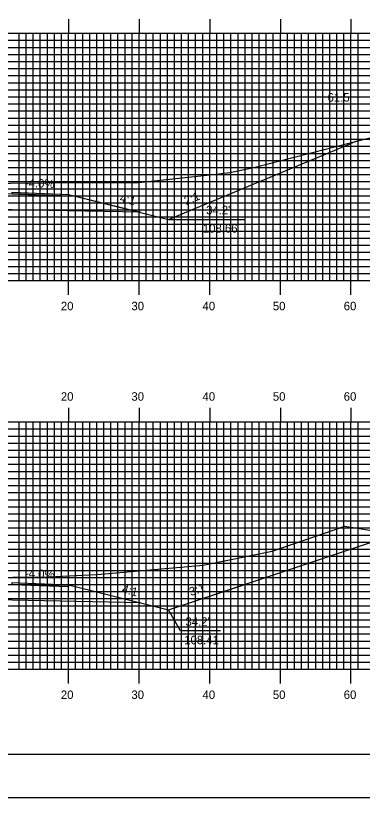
# Model space of a CAD drawing. Extents: x 1766513 to 1766856, y 442591 to 442811.
# Drawn here: x 1766691.4 to 1766740.5, y 442590.5 to 442701.2 of the extents above; entities that cross this region are included whole.
import ezdxf

# ---------------------------------------------------------------- set-up
doc = ezdxf.new("R2010")
doc.units = 0
for name, color, linetype in [('ANNOTATION', 7, 'Continuous'), ('BORDER', 7, 'Continuous'), ('D_Roadway_Centerline', 7, 'Continuous'), ('D_Roadway_Edge_Shoulder', 7, 'Continuous'), ('D_Roadway_SlopeLines', 7, 'Continuous'), ('D_Roadway_SubGrade', 7, 'Continuous'), ('D_Text_Standard', 7, 'Continuous'), ('H_V ANNOTATION', 7, 'Continuous'), ('MAJOR', 7, 'Continuous'), ('MINOR', 7, 'Continuous'), ('PDRAIN', 7, 'Continuous'), ('PLOT BOUNDARY', 7, 'Continuous'), ('S_Roadway_Centerline', 7, 'Continuous')]:
    doc.layers.add(name, color=color, linetype=linetype)

msp = doc.modelspace()

# ---------------------------------------------------------------- linework, layer by layer
at = {"layer": 'ANNOTATION'}
msp.add_lwpolyline([(1766720.43, 442614.1), (1766714.74, 442614.1), (1766713.08, 442617.08)], dxfattribs=at)
msp.add_arc((1766742.62, 442673.8), 10, 104.3672, 112.6238, dxfattribs=at)
at = {"layer": 'BORDER'}
msp.add_lwpolyline([(1766529.31, 442596.67), (1766849.31, 442596.67), (1766849.31, 442806.67), (1766529.31, 442806.67)], close=True, dxfattribs=at)
at = {"layer": 'D_Roadway_Centerline'}
msp.add_line((1766713.08, 442617.08), (1766742.93, 442627.03), dxfattribs=at)
at = {"layer": 'D_Roadway_Edge_Shoulder'}
for points in [[(1766690.91, 442676.19), (1766698.91, 442675.87), (1766698.91, 442675.62), (1766690.91, 442675.94)], [(1766690.91, 442620.94), (1766698.91, 442620.62), (1766698.91, 442620.37), (1766690.91, 442620.69)]]:
    msp.add_lwpolyline(points, close=True, dxfattribs=at)
at = {"layer": 'D_Roadway_SlopeLines'}
for points in [[(1766713.08, 442672.33), (1766738.77, 442683.03)], [(1766698.91, 442675.87), (1766713.08, 442672.33)], [(1766698.91, 442620.62), (1766713.08, 442617.08)], [(1766713.08, 442617.08), (1766723.71, 442620.62)]]:
    msp.add_lwpolyline(points, dxfattribs=at)
at = {"layer": 'D_Roadway_SubGrade'}
for points in [[(1766666.91, 442674.22), (1766648.74, 442673.86), (1766658.91, 442676.4), (1766658.91, 442676.15), (1766666.91, 442676.47), (1766678.91, 442676.21), (1766690.91, 442675.94), (1766698.91, 442675.62), (1766698.91, 442675.87), (1766709.08, 442673.33), (1766690.91, 442673.69), (1766678.91, 442673.96)], [(1766666.91, 442618.97), (1766648.74, 442618.61), (1766658.91, 442621.15), (1766658.91, 442620.9), (1766666.91, 442621.22), (1766678.91, 442620.96), (1766690.91, 442620.69), (1766698.91, 442620.37), (1766698.91, 442620.62), (1766709.08, 442618.08), (1766690.91, 442618.44), (1766678.91, 442618.71)]]:
    msp.add_lwpolyline(points, close=True, dxfattribs=at)
at = {"layer": 'MAJOR'}
for p, q in [((1766698.91, 442700.67), (1766698.91, 442698.67)), ((1766708.91, 442700.67), (1766708.91, 442698.67)), ((1766718.91, 442700.67), (1766718.91, 442698.67)), ((1766728.91, 442700.67), (1766728.91, 442698.67)), ((1766738.91, 442700.67), (1766738.91, 442698.67)), ((1766538.91, 442698.67), (1766818.91, 442698.67)), ((1766538.91, 442698.67), (1766818.91, 442698.67)), ((1766698.91, 442663.67), (1766698.91, 442698.67)), ((1766708.91, 442663.67), (1766708.91, 442698.67)), ((1766718.91, 442663.67), (1766718.91, 442698.67)), ((1766728.91, 442663.67), (1766728.91, 442698.67)), ((1766738.91, 442663.67), (1766738.91, 442698.67)), ((1766538.91, 442693.67), (1766818.91, 442693.67)), ((1766538.91, 442688.67), (1766818.91, 442688.67)), ((1766538.91, 442683.67), (1766818.91, 442683.67)), ((1766538.91, 442678.67), (1766818.91, 442678.67)), ((1766538.91, 442673.67), (1766818.91, 442673.67)), ((1766538.91, 442668.67), (1766818.91, 442668.67)), ((1766538.91, 442663.67), (1766818.91, 442663.67)), ((1766538.91, 442663.67), (1766818.91, 442663.67)), ((1766698.91, 442661.66), (1766698.91, 442663.67)), ((1766708.91, 442661.66), (1766708.91, 442663.67)), ((1766718.91, 442661.66), (1766718.91, 442663.67)), ((1766728.91, 442661.66), (1766728.91, 442663.67)), ((1766738.91, 442661.66), (1766738.91, 442663.67)), ((1766698.91, 442645.67), (1766698.91, 442643.67)), ((1766708.91, 442645.67), (1766708.91, 442643.67)), ((1766718.91, 442645.67), (1766718.91, 442643.67)), ((1766728.91, 442645.67), (1766728.91, 442643.67)), ((1766738.91, 442645.67), (1766738.91, 442643.67)), ((1766538.91, 442643.67), (1766818.91, 442643.67)), ((1766538.91, 442643.67), (1766818.91, 442643.67)), ((1766698.91, 442608.67), (1766698.91, 442643.67)), ((1766708.91, 442608.67), (1766708.91, 442643.67)), ((1766718.91, 442608.67), (1766718.91, 442643.67)), ((1766728.91, 442608.67), (1766728.91, 442643.67)), ((1766738.91, 442608.67), (1766738.91, 442643.67)), ((1766538.91, 442638.67), (1766818.91, 442638.67)), ((1766538.91, 442633.67), (1766818.91, 442633.67)), ((1766538.91, 442628.67), (1766818.91, 442628.67)), ((1766538.91, 442623.67), (1766818.91, 442623.67)), ((1766538.91, 442618.67), (1766818.91, 442618.67)), ((1766538.91, 442613.67), (1766818.91, 442613.67)), ((1766538.91, 442608.67), (1766818.91, 442608.67)), ((1766538.91, 442608.67), (1766818.91, 442608.67)), ((1766698.91, 442606.66), (1766698.91, 442608.67)), ((1766708.91, 442606.66), (1766708.91, 442608.67)), ((1766718.91, 442606.66), (1766718.91, 442608.67)), ((1766728.91, 442606.66), (1766728.91, 442608.67)), ((1766738.91, 442606.66), (1766738.91, 442608.67))]:
    msp.add_line(p, q, dxfattribs=at)
at = {"layer": 'MINOR'}
for p, q in [((1766691.91, 442663.67), (1766691.91, 442698.67)), ((1766692.91, 442663.67), (1766692.91, 442698.67)), ((1766693.91, 442663.67), (1766693.91, 442698.67)), ((1766694.91, 442663.67), (1766694.91, 442698.67)), ((1766695.91, 442663.67), (1766695.91, 442698.67)), ((1766696.91, 442663.67), (1766696.91, 442698.67)), ((1766697.91, 442663.67), (1766697.91, 442698.67)), ((1766699.91, 442663.67), (1766699.91, 442698.67)), ((1766700.91, 442663.67), (1766700.91, 442698.67)), ((1766701.91, 442663.67), (1766701.91, 442698.67)), ((1766702.91, 442663.67), (1766702.91, 442698.67)), ((1766703.91, 442663.67), (1766703.91, 442698.67)), ((1766704.91, 442663.67), (1766704.91, 442698.67)), ((1766705.91, 442663.67), (1766705.91, 442698.67)), ((1766706.91, 442663.67), (1766706.91, 442698.67)), ((1766707.91, 442663.67), (1766707.91, 442698.67)), ((1766709.91, 442663.67), (1766709.91, 442698.67)), ((1766710.91, 442663.67), (1766710.91, 442698.67)), ((1766711.91, 442663.67), (1766711.91, 442698.67)), ((1766712.91, 442663.67), (1766712.91, 442698.67)), ((1766713.91, 442663.67), (1766713.91, 442698.67)), ((1766714.91, 442663.67), (1766714.91, 442698.67)), ((1766715.91, 442663.67), (1766715.91, 442698.67)), ((1766716.91, 442663.67), (1766716.91, 442698.67)), ((1766717.91, 442663.67), (1766717.91, 442698.67)), ((1766719.91, 442663.67), (1766719.91, 442698.67)), ((1766720.91, 442663.67), (1766720.91, 442698.67)), ((1766721.91, 442663.67), (1766721.91, 442698.67)), ((1766722.91, 442663.67), (1766722.91, 442698.67)), ((1766723.91, 442663.67), (1766723.91, 442698.67)), ((1766724.91, 442663.67), (1766724.91, 442698.67)), ((1766725.91, 442663.67), (1766725.91, 442698.67)), ((1766726.91, 442663.67), (1766726.91, 442698.67)), ((1766727.91, 442663.67), (1766727.91, 442698.67)), ((1766729.91, 442663.67), (1766729.91, 442698.67)), ((1766730.91, 442663.67), (1766730.91, 442698.67)), ((1766731.91, 442663.67), (1766731.91, 442698.67)), ((1766732.91, 442663.67), (1766732.91, 442698.67)), ((1766733.91, 442663.67), (1766733.91, 442698.67)), ((1766734.91, 442663.67), (1766734.91, 442698.67)), ((1766735.91, 442663.67), (1766735.91, 442698.67)), ((1766736.91, 442663.67), (1766736.91, 442698.67)), ((1766737.91, 442663.67), (1766737.91, 442698.67)), ((1766739.91, 442663.67), (1766739.91, 442698.67)), ((1766538.91, 442697.67), (1766818.91, 442697.67)), ((1766538.91, 442696.67), (1766818.91, 442696.67)), ((1766538.91, 442695.67), (1766818.91, 442695.67)), ((1766538.91, 442694.67), (1766818.91, 442694.67)), ((1766538.91, 442692.67), (1766818.91, 442692.67)), ((1766538.91, 442691.67), (1766818.91, 442691.67)), ((1766538.91, 442690.67), (1766818.91, 442690.67)), ((1766538.91, 442689.67), (1766818.91, 442689.67)), ((1766538.91, 442687.67), (1766818.91, 442687.67)), ((1766538.91, 442686.67), (1766818.91, 442686.67)), ((1766538.91, 442685.67), (1766818.91, 442685.67)), ((1766538.91, 442684.67), (1766818.91, 442684.67)), ((1766538.91, 442682.67), (1766818.91, 442682.67)), ((1766538.91, 442681.67), (1766818.91, 442681.67)), ((1766538.91, 442680.67), (1766818.91, 442680.67)), ((1766538.91, 442679.67), (1766818.91, 442679.67)), ((1766538.91, 442677.67), (1766818.91, 442677.67)), ((1766538.91, 442676.67), (1766818.91, 442676.67)), ((1766538.91, 442675.67), (1766818.91, 442675.67)), ((1766538.91, 442674.67), (1766818.91, 442674.67)), ((1766538.91, 442672.67), (1766818.91, 442672.67)), ((1766538.91, 442671.67), (1766818.91, 442671.67)), ((1766538.91, 442670.67), (1766818.91, 442670.67)), ((1766538.91, 442669.67), (1766818.91, 442669.67)), ((1766538.91, 442667.67), (1766818.91, 442667.67)), ((1766538.91, 442666.67), (1766818.91, 442666.67)), ((1766538.91, 442665.67), (1766818.91, 442665.67)), ((1766538.91, 442664.67), (1766818.91, 442664.67)), ((1766691.91, 442608.67), (1766691.91, 442643.67)), ((1766692.91, 442608.67), (1766692.91, 442643.67)), ((1766693.91, 442608.67), (1766693.91, 442643.67)), ((1766694.91, 442608.67), (1766694.91, 442643.67)), ((1766695.91, 442608.67), (1766695.91, 442643.67)), ((1766696.91, 442608.67), (1766696.91, 442643.67)), ((1766697.91, 442608.67), (1766697.91, 442643.67)), ((1766699.91, 442608.67), (1766699.91, 442643.67)), ((1766700.91, 442608.67), (1766700.91, 442643.67)), ((1766701.91, 442608.67), (1766701.91, 442643.67)), ((1766702.91, 442608.67), (1766702.91, 442643.67)), ((1766703.91, 442608.67), (1766703.91, 442643.67)), ((1766704.91, 442608.67), (1766704.91, 442643.67)), ((1766705.91, 442608.67), (1766705.91, 442643.67)), ((1766706.91, 442608.67), (1766706.91, 442643.67)), ((1766707.91, 442608.67), (1766707.91, 442643.67)), ((1766709.91, 442608.67), (1766709.91, 442643.67)), ((1766710.91, 442608.67), (1766710.91, 442643.67)), ((1766711.91, 442608.67), (1766711.91, 442643.67)), ((1766712.91, 442608.67), (1766712.91, 442643.67)), ((1766713.91, 442608.67), (1766713.91, 442643.67)), ((1766714.91, 442608.67), (1766714.91, 442643.67)), ((1766715.91, 442608.67), (1766715.91, 442643.67)), ((1766716.91, 442608.67), (1766716.91, 442643.67)), ((1766717.91, 442608.67), (1766717.91, 442643.67)), ((1766719.91, 442608.67), (1766719.91, 442643.67)), ((1766720.91, 442608.67), (1766720.91, 442643.67)), ((1766721.91, 442608.67), (1766721.91, 442643.67)), ((1766722.91, 442608.67), (1766722.91, 442643.67)), ((1766723.91, 442608.67), (1766723.91, 442643.67)), ((1766724.91, 442608.67), (1766724.91, 442643.67)), ((1766725.91, 442608.67), (1766725.91, 442643.67)), ((1766726.91, 442608.67), (1766726.91, 442643.67)), ((1766727.91, 442608.67), (1766727.91, 442643.67)), ((1766729.91, 442608.67), (1766729.91, 442643.67)), ((1766730.91, 442608.67), (1766730.91, 442643.67)), ((1766731.91, 442608.67), (1766731.91, 442643.67)), ((1766732.91, 442608.67), (1766732.91, 442643.67)), ((1766733.91, 442608.67), (1766733.91, 442643.67)), ((1766734.91, 442608.67), (1766734.91, 442643.67)), ((1766735.91, 442608.67), (1766735.91, 442643.67)), ((1766736.91, 442608.67), (1766736.91, 442643.67)), ((1766737.91, 442608.67), (1766737.91, 442643.67)), ((1766739.91, 442608.67), (1766739.91, 442643.67)), ((1766538.91, 442642.67), (1766818.91, 442642.67)), ((1766538.91, 442641.67), (1766818.91, 442641.67)), ((1766538.91, 442640.67), (1766818.91, 442640.67)), ((1766538.91, 442639.67), (1766818.91, 442639.67)), ((1766538.91, 442637.67), (1766818.91, 442637.67)), ((1766538.91, 442636.67), (1766818.91, 442636.67)), ((1766538.91, 442635.67), (1766818.91, 442635.67)), ((1766538.91, 442634.67), (1766818.91, 442634.67)), ((1766538.91, 442632.67), (1766818.91, 442632.67)), ((1766538.91, 442631.67), (1766818.91, 442631.67)), ((1766538.91, 442630.67), (1766818.91, 442630.67)), ((1766538.91, 442629.67), (1766818.91, 442629.67)), ((1766538.91, 442627.67), (1766818.91, 442627.67)), ((1766538.91, 442626.67), (1766818.91, 442626.67)), ((1766538.91, 442625.67), (1766818.91, 442625.67)), ((1766538.91, 442624.67), (1766818.91, 442624.67)), ((1766538.91, 442622.67), (1766818.91, 442622.67)), ((1766538.91, 442621.67), (1766818.91, 442621.67)), ((1766538.91, 442620.67), (1766818.91, 442620.67)), ((1766538.91, 442619.67), (1766818.91, 442619.67)), ((1766538.91, 442617.67), (1766818.91, 442617.67)), ((1766538.91, 442616.67), (1766818.91, 442616.67)), ((1766538.91, 442615.67), (1766818.91, 442615.67)), ((1766538.91, 442614.67), (1766818.91, 442614.67)), ((1766538.91, 442612.67), (1766818.91, 442612.67)), ((1766538.91, 442611.67), (1766818.91, 442611.67)), ((1766538.91, 442610.67), (1766818.91, 442610.67)), ((1766538.91, 442609.67), (1766818.91, 442609.67))]:
    msp.add_line(p, q, dxfattribs=at)
at = {"layer": 'PDRAIN'}
msp.add_line((1766713.08, 442672.33), (1766723.86, 442672.33), dxfattribs=at)
at = {"layer": 'PLOT BOUNDARY'}
msp.add_lwpolyline([(1766513.12, 442590.55), (1766853.12, 442590.55), (1766853.12, 442810.55), (1766513.12, 442810.55)], close=True, dxfattribs=at)
at = {"layer": 'S_Roadway_Centerline'}
for points in [[(1766623.63, 442682.44), (1766637.21, 442677.84), (1766645.27, 442677.4), (1766649.17, 442676.97), (1766657.25, 442676.18), (1766657.64, 442676.16), (1766661.14, 442676.13), (1766663.07, 442676.11), (1766667.57, 442676.44), (1766668.75, 442676.8), (1766669.55, 442676.89), (1766676.5, 442677.12), (1766682.01, 442677.33), (1766690.67, 442677.46), (1766700.77, 442677.57), (1766708.39, 442677.48), (1766719.37, 442678.69), (1766721.75, 442678.96), (1766725.16, 442679.65), (1766756.32, 442687.64)], [(1766621.75, 442622.67), (1766634.14, 442621.54), (1766634.58, 442621.53), (1766653.29, 442621.23), (1766668.08, 442620.36), (1766668.67, 442620.31), (1766671.86, 442620.06), (1766672.75, 442620.03), (1766677.45, 442620.42), (1766679.57, 442620.72), (1766679.62, 442620.68), (1766689.07, 442621.45), (1766691.01, 442621.71), (1766695.11, 442621.7), (1766702.98, 442622.06), (1766717.96, 442623.39), (1766727.73, 442625.37), (1766738.03, 442628.92), (1766746.42, 442627.55)]]:
    msp.add_lwpolyline(points, dxfattribs=at)

# ---------------------------------------------------------------- texts
at = {"layer": 'ANNOTATION'}
for s, rotation, p in [('-4.0%', 357.7093, (1766692.7, 442676.92)), ('2:1', 22.6238, (1766715.57, 442674.33)), ('4:1', 345.9609, (1766706.07, 442674.85)), ('-4.0%', 357.7094, (1766692.71, 442621.67)), ('3:1', 18.438, (1766716.23, 442619.03)), ('4:1', 345.9613, (1766706.38, 442619.51))]:
    msp.add_text(s, height=1.2, rotation=rotation, dxfattribs=at).set_placement(p)
for s, p in [("34.2'", (1766718.39, 442673.05)), ('108.66', (1766717.93, 442670.45)), ("34.2'", (1766715.47, 442614.82)), ('108.41', (1766715.29, 442612.22))]:
    msp.add_text(s, height=1.2, dxfattribs=at).set_placement(p)
at = {"layer": 'D_Text_Standard'}
msp.add_text("61.5'", height=1.2, dxfattribs=at).set_placement((1766735.6, 442688.99))
at = {"layer": 'H_V ANNOTATION'}
for s, p in [('20', (1766697.82, 442659.47)), ('30', (1766707.81, 442659.47)), ('40', (1766717.88, 442659.47)), ('50', (1766727.84, 442659.47)), ('60', (1766737.88, 442659.47)), ('20', (1766697.82, 442646.67)), ('30', (1766707.81, 442646.67)), ('40', (1766717.88, 442646.67)), ('50', (1766727.84, 442646.67)), ('60', (1766737.88, 442646.67)), ('20', (1766697.82, 442604.47)), ('30', (1766707.81, 442604.47)), ('40', (1766717.88, 442604.47)), ('50', (1766727.84, 442604.47)), ('60', (1766737.88, 442604.47))]:
    msp.add_text(s, height=1.2, dxfattribs=at).set_placement(p)

doc.saveas('drawing.dxf')
